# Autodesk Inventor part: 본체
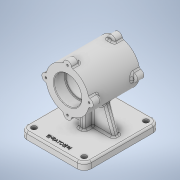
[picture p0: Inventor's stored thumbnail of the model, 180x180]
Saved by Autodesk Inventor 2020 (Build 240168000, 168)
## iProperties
Created: 2022-11
Part Number: 본체
Material: 일반
Document SubType Name: Modeling
Designer: owner
Density: 1 g/cm^3
Appearance: 기본값
Author: owner
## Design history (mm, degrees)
sketch "스케치1"
  geometry: L1 (0, 0)-(87, 0); L2 (0, 37)-(0, 23.5); L3 (0, 23.5)-(19, 23.5); L4 (19, 23.5)-(19, 21); L5 (19, 21)-(68, 21); L6 (68, 21)-(68, 23.5); L7 (68, 23.5)-(87, 23.5); L8 (87, 23.5)-(87, 37); L9 (87, 37)-(0, 37); 2 further points
  constraints: 18 end point, 7 perpendicular, 2 midpoint, 2 vertical alignment, 1 horizontal, 1 vertical
  dimensions: "d0" = 87 distance of L1.start L1.end; "d1" = 47 diameter of L7 L1; "d2" = 47 diameter of L3 L1; "d3" = 42 diameter of L5 L1; "d4" = 19 distance of L2.end L3.end; "d5" = 19 distance of L6.end L7.end; "d6" = 74 diameter of L9 L1
revolve "회전1" sketch "스케치1" stored, may be unused: angle "d7" = 90 deg
node "작업 평면1"
sketch "스케치2"
  geometry: L1 (26.5, -55)-(-103.5, -55); L2 (-103.5, -55)-(-103.5, 55); L3 (-103.5, 55)-(26.5, 55); L4 (26.5, 55)-(26.5, -55); L5 (26.5, -55)-(-103.5, 55); L6 (-103.5, -55)-(26.5, 55); L7 (0, 37)-(-87, 37) reference; 4 further points
  constraints: 12 end point, 4 midpoint, 2 parallel, 1 horizontal, 1 horizontal alignment, 1 perpendicular
  dimensions: "d9" = 130 distance of L2.end L3.end; "d10" = 110 distance of L1.end L2.end; "d11" = 70 distance from line of L4 point (-43.5, 37)
extrude "돌출1" join sketch "스케치2" distance "d12" = 12; taper "d13" = 0 deg
fillet "모깎기1" dims "d14" = 12
sketch "스케치3"
  geometry: A1 r 12 centre (-14.5, -43) between (-26.5, -43) and (-14.5, -55) reference; 2 further points
  constraints: 1 coincident
hole "구멍1" sketch "스케치3" at (-14.5, -43) diameter "d15" = 9; stored, may be unused: countersink angle "d19" = 90 deg, drill point angle "d21" = 118 deg; dims "d16" = 6, "d17" = 4, "d18" = 2, "d20" = 8
node "작업 평면2"
node "작업 평면3"
sketch "스케치5"
  geometry: L1 (-70, -43)-(-70, 43) reference; L2 (-26.964, -25.336)-(-70, -41); L3 (-70, 43)-(-70, -43) reference; L4 (-70, 41)-(-26.964, 25.336); L5 (-70, -55)-(-82, -55) reference; L6 (-70, -43)-(-70, -55) reference; L7 (-82, 55)-(-70, 55) reference; A1 r 37 centre (0, 0) between (-26.964, -25.336) and (-26.964, 25.336) reference; 3 further points
  constraints: 4 end point, 2 point on circle, 2 point on line, 1 equal length
  dimensions: "d26" = 14 distance from line of L5 L2.end; "d27" = 110 deg angle of L6 L2; "d28" = 14 distance from line of L7 L4.start
extrude "돌출2" join sketch "스케치5" stored distance "d29" = 10; taper "d30" = 0 deg
sketch "스케치6"
  geometry: L1 (-14.5, -70)-(91.5, -70) reference; L2 (23.5, -70)-(23.5, -51.412); L3 (43.5, 60.8)-(43.5, -105.8) reference; 1 further point
  constraints: 2 end point, 1 point on line, 1 vertical
  dimensions: "d31" = 20 distance between parallel lines of L2 L3
feature "리브1" sketch "스케치6" dims "d32" = 1, "d33" = 10, "d34" = 0, "d35" = 0, "d36" = 1, "d37" = 1
sketch "스케치7"
  geometry: A1 r 37 centre (0, 0) between (0, 37) and (-6.969, 36.338) reference; A2 r 7 centre (0, 37) between (6.969, 36.338) and (-6.969, 36.338); 1 further point
  constraints: 5 point on circle, 1 centre point, 1 vertical alignment
  dimensions: "d38" = 14 diameter of A2
extrude "돌출3" join sketch "스케치7" distance "d39" = 14; taper "d40" = 0 deg
sketch "스케치8"
  geometry: A1 r 37 centre (0, -37) between (-6.969, -0.662) and (6.969, -0.662) reference; A2 r 37 centre (0, -37) between (6.969, -0.662) and (-6.969, -0.662) reference; 3 further points
  constraints: 1 coincident, 1 point on circle
hole "구멍2" sketch "스케치8" at (0, 0) diameter "d41" = 3.242; stored, may be unused: countersink angle "d45" = 90 deg, drill point angle "d47" = 118 deg; dims "d42" = 8, "d43" = 4, "d44" = 2, "d46" = 10
fillet "모깎기2" dims "d51" = 3
fillet "모깎기3" dims "d52" = 3
fillet "모깎기4" dims "d53" = 3
fillet "모깎기5" dims "d54" = 3
fillet "모깎기6" dims "d55" = 3
fillet "모깎기7" dims "d56" = 1
chamfer "모따기1" distance "d57" = 1; stored, may be unused: second distance "d58" = 2, angle "d59" = 45 deg
sketch "스케치9"
  geometry: L1 (43.5, 77)-(43.5, -77) reference; L2 (-14.5, -55)-(91.5, -55) reference; 2 further points
  constraints: 1 other
  dimensions: "d60" = 58 distance from line of point (-14.5, 0) L1; "d61" = 55 distance from line of L2 point (-14.5, 0)
feature "엠보싱1" sketch "스케치9" dims "d11" = 70, "d62" = 0.5, "d63" = 0
node "솔리드1"
mirror "미러1"
mirror "미러2"
mirror "미러3"
pattern_circular "원형 패턴1" dims angle "d49" = 360 deg
mirror "미러4"
feature "A9D066F2-1C7D-4E18-AEED-F7BC21143FA4" dims "d15" = 9, "d16" = 6, "d17" = 4, "d18" = 2, "d19" = 90 deg, "d20" = 8, "d21" = 118 deg
other parameters: "d8" = -82, "d25" = 43.5
